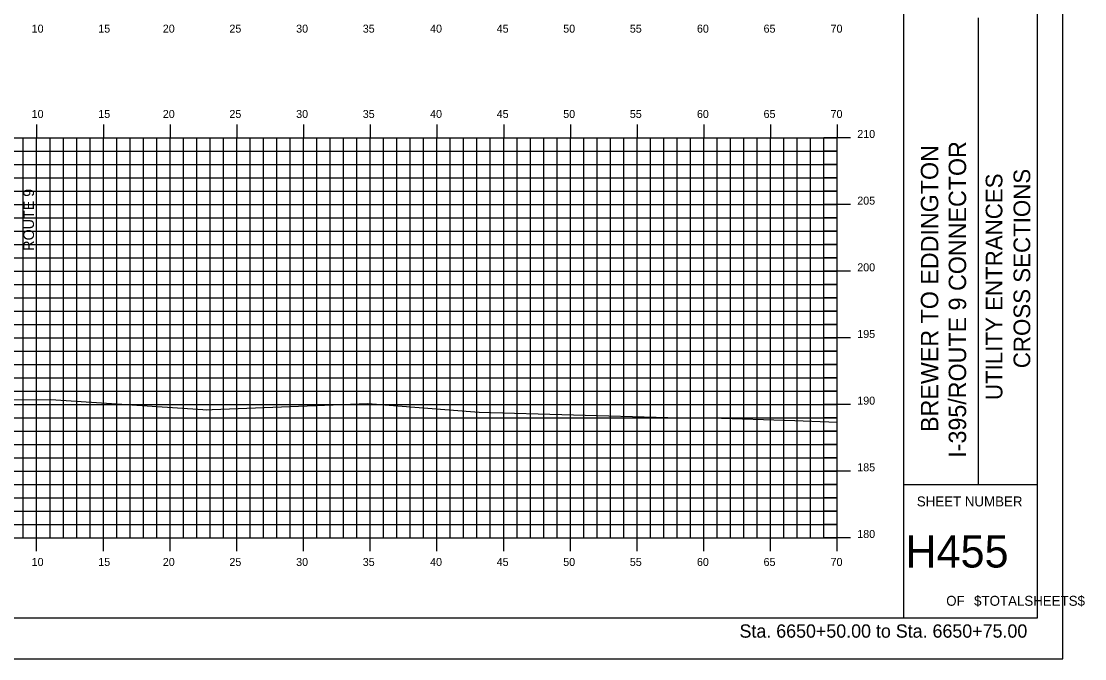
# Model space of a CAD drawing. Extents: x 1723321 to 1723493, y 458501 to 458611.
# Drawn here: x 1723412.9 to 1723492.6, y 458501.2 to 458549 of the extents above; entities that cross this region are included whole.
import ezdxf

# ---------------------------------------------------------------- set-up
doc = ezdxf.new("R2010")
doc.units = 0
for name, color, linetype in [('ANNOTATION', 7, 'Continuous'), ('BORDER', 7, 'Continuous'), ('H_V ANNOTATION', 7, 'Continuous'), ('HIGHWAY_TITLE', 7, 'Continuous'), ('MAJOR', 7, 'Continuous'), ('MINOR', 7, 'Continuous'), ('PLOT BOUNDARY', 7, 'Continuous'), ('S_Roadway_Centerline', 7, 'Continuous')]:
    doc.layers.add(name, color=color, linetype=linetype)

msp = doc.modelspace()

# ---------------------------------------------------------------- linework, layer by layer
at = {"layer": 'BORDER'}
for p, q in [((1723479.029, 458504.254), (1723479.029, 458609.254)), ((1723484.62, 458514.257), (1723484.62, 458549.257)), ((1723479.029, 458514.257), (1723489.029, 458514.257))]:
    msp.add_line(p, q, dxfattribs=at)
msp.add_lwpolyline([(1723329.029, 458504.254), (1723489.029, 458504.254), (1723489.029, 458609.254), (1723329.029, 458609.254)], close=True, dxfattribs=at)
at = {"layer": 'MAJOR'}
for p, q in [((1723414.029, 458541.256), (1723414.029, 458540.254)), ((1723419.029, 458541.256), (1723419.029, 458540.254)), ((1723424.029, 458541.256), (1723424.029, 458540.254)), ((1723429.029, 458541.256), (1723429.029, 458540.254)), ((1723434.029, 458541.256), (1723434.029, 458540.254)), ((1723439.029, 458541.256), (1723439.029, 458540.254)), ((1723444.029, 458541.256), (1723444.029, 458540.254)), ((1723449.029, 458541.256), (1723449.029, 458540.254)), ((1723454.029, 458541.256), (1723454.029, 458540.254)), ((1723459.029, 458541.256), (1723459.029, 458540.254)), ((1723464.029, 458541.256), (1723464.029, 458540.254)), ((1723469.029, 458541.256), (1723469.029, 458540.254)), ((1723474.029, 458541.256), (1723474.029, 458540.254)), ((1723334.029, 458540.254), (1723474.029, 458540.254)), ((1723334.029, 458540.254), (1723474.029, 458540.254)), ((1723414.029, 458510.254), (1723414.029, 458540.254)), ((1723419.029, 458510.254), (1723419.029, 458540.254)), ((1723424.029, 458510.254), (1723424.029, 458540.254)), ((1723429.029, 458510.254), (1723429.029, 458540.254)), ((1723434.029, 458510.254), (1723434.029, 458540.254)), ((1723439.029, 458510.254), (1723439.029, 458540.254)), ((1723444.029, 458510.254), (1723444.029, 458540.254)), ((1723449.029, 458510.254), (1723449.029, 458540.254)), ((1723454.029, 458510.254), (1723454.029, 458540.254)), ((1723459.029, 458510.254), (1723459.029, 458540.254)), ((1723464.029, 458510.254), (1723464.029, 458540.254)), ((1723469.029, 458510.254), (1723469.029, 458540.254)), ((1723475.031, 458540.254), (1723473.027, 458540.254)), ((1723474.029, 458510.254), (1723474.029, 458540.254)), ((1723474.029, 458510.254), (1723474.029, 458540.254)), ((1723334.029, 458535.254), (1723474.029, 458535.254)), ((1723475.031, 458535.254), (1723473.027, 458535.254)), ((1723334.029, 458530.254), (1723474.029, 458530.254)), ((1723475.031, 458530.254), (1723473.027, 458530.254)), ((1723334.029, 458525.254), (1723474.029, 458525.254)), ((1723475.031, 458525.254), (1723473.027, 458525.254)), ((1723334.029, 458520.254), (1723474.029, 458520.254)), ((1723475.031, 458520.254), (1723473.027, 458520.254)), ((1723334.029, 458515.254), (1723474.029, 458515.254)), ((1723475.031, 458515.254), (1723473.027, 458515.254)), ((1723334.029, 458510.254), (1723474.029, 458510.254)), ((1723334.029, 458510.254), (1723474.029, 458510.254)), ((1723414.029, 458509.252), (1723414.029, 458510.254)), ((1723419.029, 458509.252), (1723419.029, 458510.254)), ((1723424.029, 458509.252), (1723424.029, 458510.254)), ((1723429.029, 458509.252), (1723429.029, 458510.254)), ((1723434.029, 458509.252), (1723434.029, 458510.254)), ((1723439.029, 458509.252), (1723439.029, 458510.254)), ((1723444.029, 458509.252), (1723444.029, 458510.254)), ((1723449.029, 458509.252), (1723449.029, 458510.254)), ((1723454.029, 458509.252), (1723454.029, 458510.254)), ((1723459.029, 458509.252), (1723459.029, 458510.254)), ((1723464.029, 458509.252), (1723464.029, 458510.254)), ((1723469.029, 458509.252), (1723469.029, 458510.254)), ((1723475.031, 458510.254), (1723473.027, 458510.254)), ((1723474.029, 458509.252), (1723474.029, 458510.254))]:
    msp.add_line(p, q, dxfattribs=at)
at = {"layer": 'MINOR'}
for p, q in [((1723413.029, 458510.254), (1723413.029, 458540.254)), ((1723415.029, 458510.254), (1723415.029, 458540.254)), ((1723416.029, 458510.254), (1723416.029, 458540.254)), ((1723417.029, 458510.254), (1723417.029, 458540.254)), ((1723418.029, 458510.254), (1723418.029, 458540.254)), ((1723420.029, 458510.254), (1723420.029, 458540.254)), ((1723421.029, 458510.254), (1723421.029, 458540.254)), ((1723422.029, 458510.254), (1723422.029, 458540.254)), ((1723423.029, 458510.254), (1723423.029, 458540.254)), ((1723425.029, 458510.254), (1723425.029, 458540.254)), ((1723426.029, 458510.254), (1723426.029, 458540.254)), ((1723427.029, 458510.254), (1723427.029, 458540.254)), ((1723428.029, 458510.254), (1723428.029, 458540.254)), ((1723430.029, 458510.254), (1723430.029, 458540.254)), ((1723431.029, 458510.254), (1723431.029, 458540.254)), ((1723432.029, 458510.254), (1723432.029, 458540.254)), ((1723433.029, 458510.254), (1723433.029, 458540.254)), ((1723435.029, 458510.254), (1723435.029, 458540.254)), ((1723436.029, 458510.254), (1723436.029, 458540.254)), ((1723437.029, 458510.254), (1723437.029, 458540.254)), ((1723438.029, 458510.254), (1723438.029, 458540.254)), ((1723440.029, 458510.254), (1723440.029, 458540.254)), ((1723441.029, 458510.254), (1723441.029, 458540.254)), ((1723442.029, 458510.254), (1723442.029, 458540.254)), ((1723443.029, 458510.254), (1723443.029, 458540.254)), ((1723445.029, 458510.254), (1723445.029, 458540.254)), ((1723446.029, 458510.254), (1723446.029, 458540.254)), ((1723447.029, 458510.254), (1723447.029, 458540.254)), ((1723448.029, 458510.254), (1723448.029, 458540.254)), ((1723450.029, 458510.254), (1723450.029, 458540.254)), ((1723451.029, 458510.254), (1723451.029, 458540.254)), ((1723452.029, 458510.254), (1723452.029, 458540.254)), ((1723453.029, 458510.254), (1723453.029, 458540.254)), ((1723455.029, 458510.254), (1723455.029, 458540.254)), ((1723456.029, 458510.254), (1723456.029, 458540.254)), ((1723457.029, 458510.254), (1723457.029, 458540.254)), ((1723458.029, 458510.254), (1723458.029, 458540.254)), ((1723460.029, 458510.254), (1723460.029, 458540.254)), ((1723461.029, 458510.254), (1723461.029, 458540.254)), ((1723462.029, 458510.254), (1723462.029, 458540.254)), ((1723463.029, 458510.254), (1723463.029, 458540.254)), ((1723465.029, 458510.254), (1723465.029, 458540.254)), ((1723466.029, 458510.254), (1723466.029, 458540.254)), ((1723467.029, 458510.254), (1723467.029, 458540.254)), ((1723468.029, 458510.254), (1723468.029, 458540.254)), ((1723470.029, 458510.254), (1723470.029, 458540.254)), ((1723471.029, 458510.254), (1723471.029, 458540.254)), ((1723472.029, 458510.254), (1723472.029, 458540.254)), ((1723473.029, 458510.254), (1723473.029, 458540.254)), ((1723334.029, 458539.254), (1723474.029, 458539.254)), ((1723474.029, 458539.254), (1723473.027, 458539.254)), ((1723334.029, 458538.254), (1723474.029, 458538.254)), ((1723474.029, 458538.254), (1723473.027, 458538.254)), ((1723334.029, 458537.254), (1723474.029, 458537.254)), ((1723474.029, 458537.254), (1723473.027, 458537.254)), ((1723334.029, 458536.254), (1723474.029, 458536.254)), ((1723474.029, 458536.254), (1723473.027, 458536.254)), ((1723334.029, 458534.254), (1723474.029, 458534.254)), ((1723474.029, 458534.254), (1723473.027, 458534.254)), ((1723334.029, 458533.254), (1723474.029, 458533.254)), ((1723474.029, 458533.254), (1723473.027, 458533.254)), ((1723334.029, 458532.254), (1723474.029, 458532.254)), ((1723474.029, 458532.254), (1723473.027, 458532.254)), ((1723334.029, 458531.254), (1723474.029, 458531.254)), ((1723474.029, 458531.254), (1723473.027, 458531.254)), ((1723334.029, 458529.254), (1723474.029, 458529.254)), ((1723474.029, 458529.254), (1723473.027, 458529.254)), ((1723334.029, 458528.254), (1723474.029, 458528.254)), ((1723397.093, 458528.254), (1723474.029, 458528.254)), ((1723474.029, 458528.254), (1723473.027, 458528.254)), ((1723334.029, 458527.254), (1723474.029, 458527.254)), ((1723474.029, 458527.254), (1723473.027, 458527.254)), ((1723334.029, 458526.254), (1723474.029, 458526.254)), ((1723474.029, 458526.254), (1723473.027, 458526.254)), ((1723334.029, 458524.254), (1723474.029, 458524.254)), ((1723474.029, 458524.254), (1723473.027, 458524.254)), ((1723334.029, 458523.254), (1723474.029, 458523.254)), ((1723474.029, 458523.254), (1723473.027, 458523.254)), ((1723334.029, 458522.254), (1723474.029, 458522.254)), ((1723474.029, 458522.254), (1723473.027, 458522.254)), ((1723334.029, 458521.254), (1723474.029, 458521.254)), ((1723474.029, 458521.254), (1723473.027, 458521.254)), ((1723334.029, 458519.254), (1723474.029, 458519.254)), ((1723474.029, 458519.254), (1723473.027, 458519.254)), ((1723334.029, 458518.254), (1723474.029, 458518.254)), ((1723474.029, 458518.254), (1723473.027, 458518.254)), ((1723334.029, 458517.254), (1723474.029, 458517.254)), ((1723474.029, 458517.254), (1723473.027, 458517.254)), ((1723334.029, 458516.254), (1723474.029, 458516.254)), ((1723474.029, 458516.254), (1723473.027, 458516.254)), ((1723334.029, 458514.254), (1723474.029, 458514.254)), ((1723474.029, 458514.254), (1723473.027, 458514.254)), ((1723334.029, 458513.254), (1723474.029, 458513.254)), ((1723474.029, 458513.254), (1723473.027, 458513.254)), ((1723334.029, 458512.254), (1723474.029, 458512.254)), ((1723474.029, 458512.254), (1723473.027, 458512.254)), ((1723334.029, 458511.254), (1723474.029, 458511.254)), ((1723474.029, 458511.254), (1723473.027, 458511.254))]:
    msp.add_line(p, q, dxfattribs=at)
at = {"layer": 'PLOT BOUNDARY'}
msp.add_lwpolyline([(1723320.936, 458501.195), (1723490.936, 458501.195), (1723490.936, 458611.195), (1723320.936, 458611.195)], close=True, dxfattribs=at)
at = {"layer": 'S_Roadway_Centerline'}
msp.add_lwpolyline([(1723334.029, 458522.142), (1723341.667, 458521.983), (1723351.773, 458521.819), (1723354.382, 458521.764), (1723359.747, 458521.655), (1723366.618, 458521.503), (1723370.12, 458521.41), (1723378.797, 458521.182), (1723389.414, 458520.85), (1723395.439, 458520.688), (1723402.733, 458520.609), (1723408.098, 458520.587), (1723415.095, 458520.651), (1723426.488, 458519.88), (1723426.746, 458519.86), (1723427.174, 458519.88), (1723438.85, 458520.337), (1723447.205, 458519.694), (1723461.333, 458519.284), (1723464.581, 458519.256), (1723470.841, 458519.067), (1723474.029, 458518.951)], dxfattribs=at)

# ---------------------------------------------------------------- texts
at = {"layer": 'ANNOTATION'}
msp.add_text('ROUTE 9', height=0.8, rotation=90, dxfattribs=at).set_placement((1723413.83, 458531.798))
at = {"layer": 'BORDER'}
for s, p in [('CROSS SECTIONS', (1723488.493, 458522.988)), ('UTILITY ENTRANCES', (1723486.406, 458520.597))]:
    msp.add_text(s, height=1.25, rotation=90, dxfattribs=at).set_placement(p)
for s, height, p in [('SHEET NUMBER', 0.74527, (1723479.994, 458512.621)), ('H455', 2.4194, (1723479.134, 458508.037)), ('OF', 0.7453, (1723482.196, 458505.167)), ('$TOTALSHEETS$', 0.74527, (1723484.286, 458505.167))]:
    msp.add_text(s, height=height, dxfattribs=at).set_placement(p)
at = {"layer": 'H_V ANNOTATION'}
for s, height, p in [('10', 0.6, (1723413.654, 458548.154)), ('15', 0.6, (1723418.646, 458548.154)), ('20', 0.6, (1723423.483, 458548.154)), ('25', 0.6, (1723428.475, 458548.154)), ('30', 0.6, (1723433.477, 458548.154)), ('35', 0.6, (1723438.469, 458548.154)), ('40', 0.6, (1723443.515, 458548.154)), ('45', 0.6, (1723448.507, 458548.154)), ('50', 0.6, (1723453.493, 458548.154)), ('55', 0.6, (1723458.485, 458548.154)), ('60', 0.6, (1723463.515, 458548.154)), ('65', 0.6, (1723468.507, 458548.154)), ('70', 0.6, (1723473.531, 458548.154)), ('10', 0.6, (1723413.654, 458541.754)), ('15', 0.6, (1723418.646, 458541.754)), ('20', 0.6, (1723423.483, 458541.754)), ('25', 0.6, (1723428.475, 458541.754)), ('30', 0.6, (1723433.477, 458541.754)), ('35', 0.6, (1723438.469, 458541.754)), ('40', 0.6, (1723443.515, 458541.754)), ('45', 0.6, (1723448.507, 458541.754)), ('50', 0.6, (1723453.493, 458541.754)), ('55', 0.6, (1723458.485, 458541.754)), ('60', 0.6, (1723463.515, 458541.754)), ('65', 0.6, (1723468.507, 458541.754)), ('70', 0.6, (1723473.531, 458541.754)), ('210', 0.6, (1723475.529, 458540.254)), ('205', 0.6, (1723475.529, 458535.254)), ('200', 0.6, (1723475.529, 458530.254)), ('195', 0.6, (1723475.529, 458525.254)), ('190', 0.6, (1723475.529, 458520.254)), ('185', 0.6, (1723475.529, 458515.254)), ('180', 0.6, (1723475.529, 458510.254)), ('10', 0.6, (1723413.654, 458508.154)), ('15', 0.6, (1723418.646, 458508.154)), ('20', 0.6, (1723423.483, 458508.154)), ('25', 0.6, (1723428.475, 458508.154)), ('30', 0.6, (1723433.477, 458508.154)), ('35', 0.6, (1723438.469, 458508.154)), ('40', 0.6, (1723443.515, 458508.154)), ('45', 0.6, (1723448.507, 458508.154)), ('50', 0.6, (1723453.493, 458508.154)), ('55', 0.6, (1723458.485, 458508.154)), ('60', 0.6, (1723463.515, 458508.154)), ('65', 0.6, (1723468.507, 458508.154)), ('70', 0.6, (1723473.531, 458508.154)), ('Sta. 6650+50.00 to Sta. 6650+75.00', 1.0002, (1723466.705, 458502.774))]:
    msp.add_text(s, height=height, dxfattribs=at).set_placement(p)
at = {"layer": 'HIGHWAY_TITLE'}
for s, p in [('BREWER TO EDDINGTON', (1723481.601, 458518.206)), ('I-395/ROUTE 9 CONNECTOR', (1723483.688, 458516.273))]:
    msp.add_text(s, height=1.30428, rotation=90, dxfattribs=at).set_placement(p)

doc.saveas('drawing.dxf')
